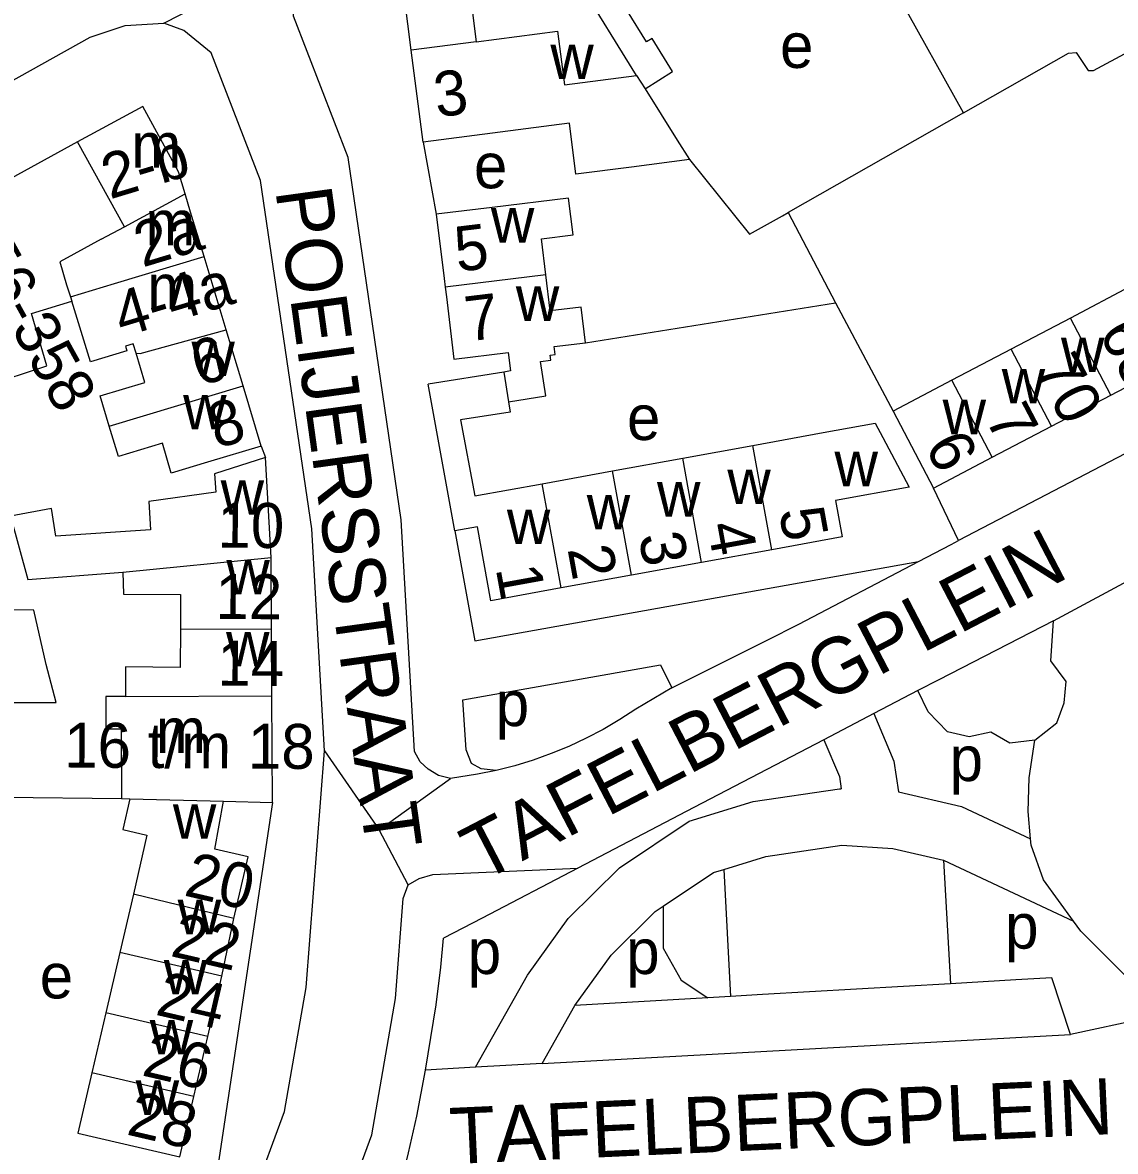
# Model space of a CAD drawing. Extents: x 163012 to 165277, y 382513 to 383987.
# Drawn here: x 163402 to 163499.2, y 383543.8 to 383644.3 of the extents above; entities that cross this region are included whole.
import ezdxf

# ---------------------------------------------------------------- set-up
doc = ezdxf.new("R2010")
doc.units = 0
for name, color, linetype in [('BLT_Basislijn', 7, 'Continuous'), ('BLT_Bebouwing', 7, 'Continuous'), ('BLT_Centroide', 7, 'Continuous'), ('BLT_Huisnummer', 7, 'Continuous'), ('BLT_Huisnummer_ tussenligend', 7, 'Continuous'), ('BLT_Huisnummer_reeks', 7, 'Continuous'), ('BLT_Onderverdeling_panden', 7, 'Continuous'), ('BLT_Straatnaam', 7, 'Continuous'), ('BLT_Vlakafsluiter', 7, 'Continuous')]:
    doc.layers.add(name, color=color, linetype=linetype)

msp = doc.modelspace()

# ---------------------------------------------------------------- linework, layer by layer
at = {"layer": 'BLT_Basislijn'}
for p, q in [((163485.71, 383636.26), (163474.39, 383656.6)), ((163576.22, 383645.71), (163485.28, 383598.2)), ((163485.71, 383636.26), (163470.12, 383627.38)), ((163437.63, 383633.64), (163438.8, 383627.24)), ((163470.12, 383627.38), (163474.34, 383619.35)), ((163452.08, 383615.81), (163474.34, 383619.35)), ((163474.34, 383619.35), (163479.45, 383609.72)), ((163423.21, 383606.61), (163423.61, 383605.6)), ((163485.28, 383598.2), (163483.05, 383602.86)), ((163493.74, 383591.05), (163501.69, 383595.36)), ((163468.24, 383589.34), (163471.07, 383590.75)), ((163459.76, 383585.11), (163468.24, 383589.34)), ((163483.52, 383585.82), (163481.66, 383584.85)), ((163481.66, 383584.85), (163477.74, 383582.8)), ((163477.74, 383582.8), (163473.29, 383580.48)), ((163473.29, 383580.48), (163461.73, 383574.45)), ((163400.32, 383575.36), (163410.8, 383575.24)), ((163461.73, 383574.45), (163451.39, 383569.05)), ((163483.95, 383569.77), (163484.57, 383558.77)), ((163451.39, 383569.05), (163442.87, 383564.6)), ((163464.38, 383568.94), (163464.98, 383557.64)), ((163442.87, 383564.6), (163439.45, 383562.82)), ((163442.28, 383551.33), (163446.91, 383559.54)), ((163484.57, 383558.77), (163467.83, 383557.8)), ((163490.36, 383559.1), (163484.57, 383558.77)), ((163493.57, 383559.28), (163490.36, 383559.1)), ((163495.25, 383554.24), (163493.57, 383559.28)), ((163464.98, 383557.64), (163462.96, 383557.52)), ((163467.83, 383557.8), (163464.98, 383557.64)), ((163448.21, 383551.67), (163451.13, 383556.84)), ((163462.96, 383557.52), (163451.13, 383556.84)), ((163448.21, 383551.67), (163495.25, 383554.24)), ((163448.21, 383551.67), (163442.28, 383551.33)), ((163442.28, 383551.33), (163437.85, 383551.07))]:
    msp.add_line(p, q, dxfattribs=at)
for points in [[(163485.71, 383636.26), (163495.05, 383641.57), (163495.75, 383641.62), (163496.81, 383640.02), (163497.28, 383640.02), (163554.26, 383670.71)], [(163440.05, 383577.02), (163439.01, 383577.29), (163438.07, 383577.85), (163437.35, 383578.5), (163436.86, 383579.42), (163435.68, 383600.04), (163430.96, 383632.29), (163426.08, 383644.86), (163425.95, 383647.16), (163426.37, 383649.07), (163427.43, 383650.86)], [(163359.07, 383620.99), (163368.14, 383623.26), (163374.34, 383624.82), (163375.27, 383627.45), (163385.2, 383631.18), (163394.04, 383635.21), (163408, 383643), (163411.11, 383644.02), (163414.54, 383644.24)], [(163428.84, 383579.5), (163427.71, 383599.23), (163423.17, 383630.24), (163418.77, 383641.59), (163416.33, 383643.59), (163414.54, 383644.24)], [(163461.34, 383632.11), (163466.68, 383625.46), (163469.61, 383627.09), (163470.12, 383627.38)], [(163440.46, 383599.06), (163442.23, 383589.29), (163481.72, 383596.33)], [(163481.72, 383596.33), (163484.62, 383597.85), (163485.28, 383598.2)], [(163471.07, 383590.75), (163481.72, 383596.33)], [(163493.74, 383591.05), (163483.52, 383585.82)], [(163492.08, 383580.44), (163494.02, 383581.99), (163494.69, 383583.76), (163494.85, 383585.65), (163493.49, 383587.51), (163493.74, 383591.05)], [(163444.13, 383577.74), (163442.79, 383577.89), (163441.92, 383578.37), (163441.45, 383579.58), (163441.17, 383584.02), (163458.74, 383587.15), (163459.76, 383585.11)], [(163459.76, 383585.11), (163456.56, 383583.2), (163455.13, 383582.27), (163453.65, 383581.4), (163452.15, 383580.61), (163450.6, 383579.89), (163449.02, 383579.24), (163447.42, 383578.66), (163445.79, 383578.16)], [(163492.08, 383580.44), (163489.85, 383580.16), (163488.14, 383581.14), (163486.21, 383580.74), (163484.29, 383581.17), (163482.56, 383582.95), (163481.66, 383584.85)], [(163477.74, 383582.8), (163479.52, 383578.56), (163479.93, 383575.83)], [(163473.29, 383580.48), (163474.67, 383577.2), (163474.83, 383576.11)], [(163491.69, 383571.65), (163491.46, 383574.08), (163491.56, 383577.09), (163492.08, 383580.44)], [(163416.42, 383536.6), (163418.83, 383535.99), (163420.83, 383536.28), (163422.47, 383539.75), (163425.29, 383547.41), (163427.22, 383558.44), (163428.84, 383579.5)], [(163444.13, 383577.74), (163442.46, 383577.4), (163440.05, 383577.02)], [(163445.79, 383578.16), (163444.13, 383577.74)], [(163446.91, 383559.54), (163450.55, 383564.58), (163455.11, 383569.08), (163461.3, 383573.22), (163467.01, 383574.98), (163474.67, 383576.12), (163474.83, 383576.11)], [(163479.93, 383575.83), (163485.53, 383574.55), (163491.69, 383571.65)], [(163424.22, 383574.9), (163419.29, 383542.11), (163417.13, 383536.78), (163416.42, 383536.6)], [(163464.38, 383568.94), (163468.12, 383570.09), (163474.88, 383571.1), (163479.44, 383570.81), (163483.95, 383569.77)], [(163495.52, 383564.32), (163492.83, 383568.02), (163491.74, 383571.09), (163491.69, 383571.65)], [(163483.95, 383569.77), (163495.52, 383564.32)], [(163436.29, 383567.57), (163437.29, 383568.14), (163438.5, 383568.49), (163451.39, 383569.05)], [(163458.98, 383565.66), (163463.47, 383568.65), (163464.38, 383568.94)], [(163422.02, 383520.11), (163429.85, 383536.64), (163433.05, 383545.32), (163435.17, 383557.44), (163435.85, 383566.35), (163436.29, 383567.57)], [(163451.13, 383556.84), (163454.36, 383561.32), (163458.28, 383565.19), (163458.98, 383565.66)], [(163458.98, 383565.66), (163458.98, 383561.94), (163460.58, 383559.09), (163462.96, 383557.52)], [(163501.86, 383555.67), (163501.09, 383558.51), (163496.17, 383563.43), (163495.52, 383564.32)], [(163437.85, 383551.07), (163438.78, 383556.9), (163439.19, 383560.23), (163439.45, 383562.82)], [(163501.86, 383555.67), (163495.25, 383554.24)], [(163435.53, 383540.46), (163436.34, 383543.72), (163437.07, 383546.99), (163437.85, 383551.07)]]:
    msp.add_lwpolyline(points, dxfattribs=at)
at = {"layer": 'BLT_Bebouwing'}
for p, q in [((163436.57, 383641.83), (163435.69, 383648.58)), ((163442.02, 383645.16), (163442.35, 383642.59)), ((163437.63, 383633.64), (163436.57, 383641.83)), ((163412.67, 383636.83), (163406.88, 383633.67)), ((163406.88, 383633.67), (163394.6, 383626.96)), ((163418.13, 383623.47), (163416.94, 383627.42)), ((163420.09, 383616.96), (163418.13, 383623.47)), ((163500.5, 383620.77), (163495.23, 383618)), ((163495.23, 383618), (163489.95, 383615.24)), ((163421.6, 383611.97), (163420.09, 383616.96)), ((163489.95, 383615.24), (163484.68, 383612.47)), ((163498.83, 383611.14), (163504.1, 383613.91)), ((163444.81, 383613.2), (163438.08, 383612.13)), ((163423.21, 383606.61), (163421.6, 383611.97)), ((163484.68, 383612.47), (163479.45, 383609.72)), ((163493.56, 383608.37), (163498.83, 383611.14)), ((163488.28, 383605.61), (163493.56, 383608.37)), ((163466.98, 383606.67), (163473.23, 383607.81)), ((163460.73, 383605.53), (163466.98, 383606.67)), ((163424.11, 383596.68), (163423.61, 383605.6)), ((163454.47, 383604.4), (163460.73, 383605.53)), ((163483.05, 383602.86), (163488.28, 383605.61)), ((163448.22, 383603.26), (163454.47, 383604.4)), ((163468.67, 383597.39), (163462.41, 383596.25)), ((163424.14, 383590.33), (163424.11, 383596.68)), ((163462.41, 383596.25), (163456.16, 383595.12)), ((163456.16, 383595.12), (163449.91, 383593.98)), ((163424.17, 383584.39), (163424.14, 383590.33)), ((163424.22, 383574.9), (163424.17, 383584.39)), ((163410.8, 383575.24), (163411.53, 383575.23)), ((163419.86, 383575.01), (163424.22, 383574.9)), ((163411.84, 383566.73), (163410.63, 383561.55)), ((163419.71, 383559.43), (163420.79, 383564.56)), ((163410.63, 383561.55), (163409.38, 383556.19)), ((163418.47, 383554.08), (163419.71, 383559.43)), ((163409.38, 383556.19), (163408.14, 383550.83)), ((163417.22, 383548.72), (163418.47, 383554.08))]:
    msp.add_line(p, q, dxfattribs=at)
for points in [[(163456.63, 383639.59), (163451.48, 383647.92), (163452.35, 383648.42), (163450.37, 383651.84), (163447.86, 383656.17)], [(163457.38, 383638.41), (163459.81, 383639.94), (163458, 383642.88), (163457.5, 383642.57), (163455.81, 383645.31), (163459.11, 383647.4), (163456.99, 383650.83), (163457.6, 383651.18)], [(163442.35, 383642.59), (163449.59, 383643.53), (163450.21, 383638.76), (163456.63, 383639.59)], [(163457.38, 383638.41), (163460.25, 383633.84), (163461.34, 383632.11)], [(163416.45, 383629.04), (163415.85, 383631.02), (163412.67, 383636.83)], [(163461.34, 383632.11), (163456.18, 383631.44), (163451.22, 383630.8), (163450.64, 383635.33), (163437.63, 383633.64)], [(163416.94, 383627.42), (163416.45, 383629.04)], [(163448.55, 383621.84), (163448.16, 383625.06), (163450.98, 383625.4), (163450.58, 383628.66), (163443.76, 383627.84), (163438.8, 383627.24)], [(163438.8, 383627.24), (163439.51, 383621.53), (163439.6, 383620.76)], [(163452.08, 383615.81), (163451.7, 383618.96), (163448.93, 383618.63), (163448.55, 383621.84)], [(163439.6, 383620.76), (163439.7, 383619.89), (163440.36, 383614.35)], [(163400.52, 383612.57), (163404.13, 383613.74), (163402.78, 383618.4), (163406.37, 383619.49)], [(163412.08, 383614.87), (163411.82, 383615.7), (163411.14, 383615.5), (163411.26, 383615.09), (163408.02, 383614.11), (163406.37, 383619.49)], [(163440.36, 383614.35), (163445.19, 383614.93), (163445.39, 383613.29), (163444.81, 383613.2)], [(163445.23, 383610.56), (163448.54, 383611.09), (163448.06, 383614.14), (163448.98, 383614.25), (163448.93, 383614.69), (163449.38, 383614.75), (163449.29, 383615.47), (163452.08, 383615.81)], [(163409.69, 383608.38), (163408.88, 383611.08), (163412.86, 383612.28), (163412.08, 383614.87)], [(163440.46, 383599.06), (163438.08, 383612.13)], [(163445.23, 383610.56), (163445.38, 383609.64), (163440.95, 383608.93), (163442.23, 383602.17), (163448.22, 383603.26)], [(163479.45, 383609.72), (163483.05, 383602.86)], [(163423.21, 383606.61), (163418.43, 383605.17), (163415.22, 383604.2), (163414.42, 383606.86), (163410.51, 383605.68), (163409.69, 383608.38)], [(163473.23, 383607.81), (163477.86, 383608.65), (163478.54, 383607.37), (163480.88, 383602.96), (163474.33, 383601.76)], [(163423.61, 383605.6), (163419.06, 383604.15), (163419.18, 383602.5), (163413.21, 383601.68), (163413.38, 383599.16), (163404.95, 383598.59), (163404.55, 383601.05), (163400.92, 383600.36), (163402.46, 383594.74), (163410.89, 383595.38)], [(163474.33, 383601.76), (163474.92, 383598.53), (163468.67, 383597.39)], [(163449.91, 383593.98), (163443.66, 383592.84), (163442.46, 383599.43), (163440.46, 383599.06)], [(163393.29, 383582.03), (163400.82, 383582.33), (163400.82, 383583.8), (163404.96, 383583.8), (163404.07, 383587.16), (163402.99, 383592), (163391.5, 383592.04), (163390.69, 383595.23)], [(163410.89, 383595.38), (163410.97, 383593.43), (163416.05, 383593.4), (163416.03, 383590.35)], [(163416.03, 383590.35), (163416.01, 383586.92), (163411.14, 383586.95), (163411.13, 383584.32)], [(163411.13, 383584.32), (163409.39, 383584.32), (163409.4, 383581.44), (163410.77, 383581.45), (163410.8, 383575.24)], [(163411.53, 383575.23), (163410.9, 383572.5), (163413.05, 383571.98), (163411.84, 383566.73)], [(163420.79, 383564.56), (163422.07, 383570.05), (163419.1, 383570.75), (163419.86, 383575.01)], [(163408.14, 383550.83), (163406.89, 383545.47), (163415.98, 383543.36), (163417.22, 383548.72)]]:
    msp.add_lwpolyline(points, dxfattribs=at)
at = {"layer": 'BLT_Onderverdeling_panden'}
for p, q in [((163442.35, 383642.59), (163436.57, 383641.83)), ((163456.63, 383639.59), (163457.38, 383638.41)), ((163411.05, 383626.13), (163406.88, 383633.67)), ((163411.05, 383626.13), (163416.45, 383629.04)), ((163408.97, 383625.01), (163411.05, 383626.13)), ((163410.16, 383621.07), (163418.13, 383623.47)), ((163406.26, 383619.89), (163410.16, 383621.07)), ((163448.55, 383621.84), (163439.6, 383620.76)), ((163406.26, 383619.89), (163406.37, 383619.49)), ((163498.83, 383611.14), (163495.23, 383618)), ((163493.56, 383608.37), (163489.95, 383615.24)), ((163444.81, 383613.2), (163445.23, 383610.56)), ((163409.69, 383608.38), (163421.6, 383611.97)), ((163488.28, 383605.61), (163484.68, 383612.47)), ((163468.67, 383597.39), (163466.98, 383606.67)), ((163462.41, 383596.25), (163460.73, 383605.53)), ((163456.16, 383595.12), (163454.47, 383604.4)), ((163449.91, 383593.98), (163448.22, 383603.26)), ((163410.89, 383595.38), (163424.11, 383596.68)), ((163416.03, 383590.35), (163424.14, 383590.33)), ((163411.13, 383584.32), (163424.17, 383584.39)), ((163411.53, 383575.23), (163419.86, 383575.01)), ((163420.79, 383564.56), (163411.84, 383566.73)), ((163419.71, 383559.43), (163410.63, 383561.55)), ((163418.47, 383554.08), (163409.38, 383556.19)), ((163417.22, 383548.72), (163408.14, 383550.83))]:
    msp.add_line(p, q, dxfattribs=at)
for points in [[(163408.97, 383625.01), (163406.54, 383623.69), (163405.31, 383623.01), (163405.9, 383620.96), (163406.26, 383619.89)], [(163412.08, 383614.87), (163412.46, 383614.85), (163420.09, 383616.96)]]:
    msp.add_lwpolyline(points, dxfattribs=at)
at = {"layer": 'BLT_Vlakafsluiter'}
for p, q in [((163414.54, 383644.24), (163427.43, 383650.86)), ((163428.84, 383579.5), (163433.73, 383572.47)), ((163433.73, 383572.47), (163440.05, 383577.02)), ((163436.29, 383567.57), (163433.73, 383572.47))]:
    msp.add_line(p, q, dxfattribs=at)

# ---------------------------------------------------------------- texts
at = {"layer": 'BLT_Centroide'}
for s, p in [('e', (163469.39, 383640.26)), ('w', (163448.95, 383639.27)), ('m', (163411.66, 383631.38)), ('e', (163442.15, 383629.55)), ('m', (163412.91, 383624.47)), ('w', (163443.66, 383624.72)), ('m', (163413.07, 383618.78)), ('w', (163445.88, 383617.75)), ('w', (163417.01, 383612.84)), ('w', (163494.39, 383613.19)), ('w', (163489.12, 383610.41)), ('w', (163416.27, 383608.09)), ('e', (163455.77, 383607.15)), ('w', (163483.86, 383607.66)), ('w', (163474.24, 383603.03)), ('w', (163464.7, 383601.45)), ('w', (163419.61, 383600.5)), ('w', (163458.44, 383600.33)), ('w', (163452.19, 383599.19)), ('w', (163445.08, 383597.89)), ('w', (163420.12, 383593.41)), ('w', (163420.09, 383587)), ('p', (163444.09, 383581.69)), ('m', (163413.85, 383579.29)), ('p', (163484.48, 383576.8)), ('w', (163415.36, 383571.66)), ('w', (163415.79, 383563.16)), ('p', (163489.42, 383561.89)), ('p', (163441.6, 383559.63)), ('p', (163455.7, 383559.63)), ('w', (163414.55, 383557.81)), ('e', (163403.51, 383557.46)), ('w', (163413.3, 383552.47)), ('w', (163412.05, 383547.09))]:
    msp.add_text(s, height=4, dxfattribs=at).set_placement(p)
at = {"layer": 'BLT_Huisnummer'}
for s, rotation, p in [('3', 7.4096, (163438.85, 383635.85)), ('2a', 16.7928, (163412.65, 383622.49)), ('5', 6.9019, (163440.67, 383622.11)), ('7', 6.9073, (163441.59, 383615.91)), ('70', 297.6982, (163491.96, 383613.49)), ('8', 16.7893, (163419.24, 383606.35)), ('7', 297.6982, (163487.6, 383609.07)), ('6', 297.718, (163482.22, 383606.59)), ('5', 280.2955, (163469.28, 383600.86)), ('3', 280.3032, (163456.79, 383598.63)), ('4', 280.3032, (163462.9, 383599.58)), ('2', 280.3032, (163450.47, 383597.46)), ('1', 280.3056, (163444.08, 383595.72)), ('12', 359.6628, (163419.13, 383591.23)), ('20', 346.9101, (163416.24, 383566.64)), ('24', 346.9114, (163413.7, 383556.03)), ('28', 346.9114, (163411.13, 383545.37))]:
    msp.add_text(s, height=4, rotation=rotation, dxfattribs=at).set_placement(p)
at = {"layer": 'BLT_Huisnummer_ tussenligend'}
for s, rotation, p in [('68', 297.697, (163497.71, 383616.71)), ('6', 16.7928, (163417.7, 383611.9)), ('10', 359.6628, (163419.31, 383597.57)), ('14', 359.6628, (163419.31, 383585.29)), ('22', 346.9101, (163415.03, 383561.25)), ('26', 346.9114, (163412.49, 383550.63))]:
    msp.add_text(s, height=4, rotation=rotation, dxfattribs=at).set_placement(p)
at = {"layer": 'BLT_Huisnummer_reeks'}
for s, rotation, p in [('2-b', 16.7995, (163409.75, 383628.55)), ('356-358', 298.9842, (163395.73, 383626.48)), ('4-4a', 16.7954, (163410.84, 383616.27)), ('16 t/m 18', 359.6506, (163405.67, 383578.01))]:
    msp.add_text(s, height=4, rotation=rotation, dxfattribs=at).set_placement(p)
at = {"layer": 'BLT_Straatnaam'}
for s, height, rotation, p in [('POEIJERSSTRAAT', 4.9999, 277.8637, (163424.47, 383629.36)), ('TAFELBERGPLEIN', 5, 27.4544, (163442.81, 383567.76)), ('TAFELBERGPLEIN', 5, 2.6018, (163440.09, 383542.71))]:
    msp.add_text(s, height=height, rotation=rotation, dxfattribs=at).set_placement(p)

doc.saveas('drawing.dxf')
